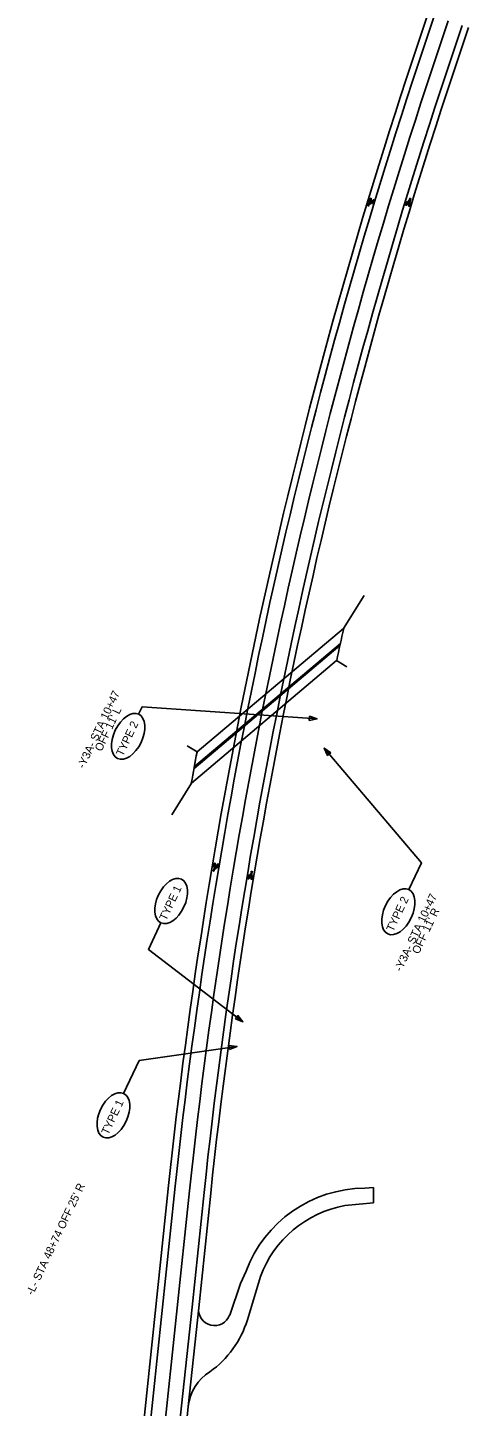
# Model space of a CAD drawing. Extents: x 553958 to 562499, y 493978 to 516388.
# Drawn here: x 561127 to 561457, y 496087 to 497120 of the extents above; entities that cross this region are included whole.
import ezdxf

# ---------------------------------------------------------------- set-up
doc = ezdxf.new("R2010")
doc.units = 0
for name, color, linetype in [('Default', 7, 'Continuous'), ('Prop DSN Text', 7, 'Continuous'), ('Prop EOT', 7, 'Continuous'), ('Prop Horizontal Alignment Tick Small', 7, 'Continuous'), ('Prop SS Fill Line', 7, 'Continuous'), ('Sheet Plan CELL', 7, 'Continuous'), ('Sheet Plot Border Inside CELL', 7, 'Continuous'), ('Sheet Plot Border Outside CELL', 7, 'Continuous')]:
    doc.layers.add(name, color=color, linetype=linetype)

msp = doc.modelspace()

# ---------------------------------------------------------------- linework, layer by layer
at = {"layer": 'Default'}
for p, q in [((561363.7, 496669.9), (561379.1, 496694.6)), ((561254, 496577.2), (561363.7, 496669.9)), ((561251.7, 496564.7), (561360.9, 496657)), ((561252, 496566.3), (561361.3, 496658.6)), ((561249.7, 496553.9), (561358.5, 496645.8)), ((561358.5, 496645.8), (561366.1, 496641.1)), ((561246.5, 496581.8), (561254, 496577.2)), ((561235, 496530.2), (561249.7, 496553.9))]:
    msp.add_line(p, q, dxfattribs=at)
for centre, radius, start, end in [((565242.2, 495812.8), 3972, 167.5396, 167.8948), ((565213, 495835.1), 4028, 169.3836, 169.72)]:
    msp.add_arc(centre, radius, start, end, dxfattribs=at)
at = {"layer": 'Prop DSN Text'}
for centre, major_axis, ratio in [((561202.4, 496588.9), (7.9, 16.6), 0.581481), ((561234.6, 496465.5), (7.7, 16.4), 0.582717), ((561404.7, 496457.4), (7.9, 16.6), 0.581481), ((561191.3, 496304.8), (7.7, 16.4), 0.582717)]:
    msp.add_ellipse(centre, major_axis=major_axis, ratio=ratio, dxfattribs=at)
at = {"layer": 'Prop EOT'}
for p, q in [((561250.2, 496160.9), (561242.4, 496087.1)), ((561247.4, 496086.6), (561255.2, 496160.4))]:
    msp.add_line(p, q, dxfattribs=at)
at = {"layer": 'Prop Horizontal Alignment Tick Small'}
for p, q in [((561383, 496991.4), (561383.2, 496991.2)), ((561383, 496991.4), (561383.2, 496991.2)), ((561383, 496989.3), (561384.6, 496990.7)), ((561384.8, 496990.5), (561383.3, 496989.2)), ((561383.9, 496990.8), (561384.1, 496990.7)), ((561383.9, 496990.8), (561384.1, 496990.7)), ((561384.6, 496990.7), (561384.8, 496990.5)), ((561413.3, 496990.9), (561412.1, 496990.1)), ((561412.1, 496990.1), (561412.2, 496990.4)), ((561412.2, 496990.4), (561413.3, 496991.2)), ((561413, 496991.9), (561413.2, 496991.9)), ((561413, 496991.9), (561413.2, 496991.9)), ((561413, 496989.8), (561413.3, 496990.9)), ((561413.3, 496991.2), (561413.7, 496991.2)), ((561413.7, 496991.2), (561413.3, 496989.5)), ((561413.9, 496991.6), (561414.1, 496991.6)), ((561413.9, 496991.6), (561414.1, 496991.6)), ((561381.9, 496987.4), (561381.8, 496987.5)), ((561381.9, 496987.4), (561381.8, 496987.5)), ((561382.3, 496987.8), (561383, 496989.3)), ((561382.6, 496987.7), (561382.3, 496987.8)), ((561383.9, 496988.2), (561382.6, 496987.7)), ((561382.8, 496986.9), (561382.6, 496987)), ((561382.8, 496986.9), (561382.6, 496987)), ((561383.2, 496989), (561382.7, 496988)), ((561382.7, 496988), (561384, 496988.4)), ((561384.2, 496988.9), (561383.2, 496989)), ((561383.3, 496989.2), (561384.1, 496989.1)), ((561384, 496988.4), (561383.9, 496988.2)), ((561384.1, 496989.1), (561384.3, 496989.7)), ((561384.5, 496989.7), (561384.2, 496988.9)), ((561384.3, 496989.7), (561384.5, 496989.7)), ((561385.1, 496990.2), (561385.3, 496990)), ((561385.1, 496990.2), (561385.3, 496990)), ((561386, 496989.6), (561386.2, 496989.5)), ((561386, 496989.6), (561386.2, 496989.5)), ((561410.5, 496988.5), (561410.3, 496988.6)), ((561410.5, 496988.5), (561410.3, 496988.6)), ((561411.5, 496988.2), (561411.3, 496988.3)), ((561411.5, 496988.2), (561411.3, 496988.3)), ((561411.8, 496988), (561413, 496989.6)), ((561412, 496987.8), (561411.8, 496987.9)), ((561412, 496989.7), (561413, 496989.8)), ((561412, 496988.9), (561412, 496989.7)), ((561413.3, 496989.5), (561412, 496987.8)), ((561412.2, 496988.8), (561412, 496988.9)), ((561413, 496989.6), (561412.2, 496989.5)), ((561412.2, 496989.5), (561412.2, 496988.8)), ((561412.8, 496987.8), (561412.6, 496987.9)), ((561412.8, 496987.8), (561412.6, 496987.9)), ((561413.8, 496987.5), (561413.6, 496987.6)), ((561413.8, 496987.5), (561413.6, 496987.6)), ((561266.1, 496488.6), (561266, 496488.7)), ((561266.1, 496488.6), (561266, 496488.7)), ((561266.2, 496492.7), (561266.5, 496492.7)), ((561266.2, 496492.7), (561266.5, 496492.7)), ((561266.4, 496489.1), (561266.8, 496490.7)), ((561266.7, 496489.1), (561266.4, 496489.1)), ((561267.9, 496489.8), (561266.7, 496489.1)), ((561266.8, 496490.7), (561268, 496492.4)), ((561267, 496490.5), (561266.8, 496489.4)), ((561266.8, 496489.4), (561268, 496490.1)), ((561267, 496488.4), (561266.9, 496488.4)), ((561267, 496488.4), (561266.9, 496488.4)), ((561268.2, 496492.3), (561267, 496490.7)), ((561267, 496490.7), (561267.8, 496490.8)), ((561268, 496490.6), (561267, 496490.5)), ((561267.2, 496492.4), (561267.5, 496492.3)), ((561267.2, 496492.4), (561267.5, 496492.3)), ((561267.8, 496490.8), (561267.9, 496491.4)), ((561267.9, 496491.4), (561268.1, 496491.4)), ((561268, 496490.1), (561267.9, 496489.8)), ((561268, 496492.4), (561268.2, 496492.3)), ((561268.1, 496491.4), (561268, 496490.6)), ((561268.6, 496492), (561268.8, 496491.9)), ((561268.6, 496492), (561268.8, 496491.9)), ((561269.6, 496491.7), (561269.8, 496491.6)), ((561269.6, 496491.7), (561269.8, 496491.6)), ((561293.6, 496484.9), (561294.6, 496485.1)), ((561293.6, 496483.2), (561294.6, 496484.9)), ((561293.6, 496484.1), (561293.6, 496484.9)), ((561293.9, 496484.1), (561293.6, 496484.1)), ((561293.7, 496485.7), (561294.8, 496486.5)), ((561294.8, 496486.2), (561293.7, 496485.4)), ((561293.7, 496485.4), (561293.7, 496485.7)), ((561294.9, 496484.9), (561293.8, 496483)), ((561294.6, 496484.9), (561293.9, 496484.7)), ((561293.9, 496484.7), (561293.9, 496484.1)), ((561294.4, 496487.2), (561294.5, 496487.2)), ((561294.4, 496487.2), (561294.5, 496487.2)), ((561294.6, 496485.1), (561294.8, 496486.2)), ((561294.8, 496486.5), (561295.1, 496486.5)), ((561295.1, 496486.5), (561294.9, 496484.9)), ((561295.3, 496487), (561295.5, 496487)), ((561295.3, 496487), (561295.5, 496487)), ((561292.2, 496483.6), (561292, 496483.6)), ((561292.2, 496483.6), (561292, 496483.6)), ((561293.2, 496483.4), (561293, 496483.4)), ((561293.2, 496483.4), (561293, 496483.4)), ((561293.8, 496483), (561293.6, 496483.1)), ((561294.6, 496483.1), (561294.4, 496483.2)), ((561294.6, 496483.1), (561294.4, 496483.2)), ((561295.6, 496482.9), (561295.4, 496483)), ((561295.6, 496482.9), (561295.4, 496483))]:
    msp.add_line(p, q, dxfattribs=at)
for centre, radius, start, end in [((561413.5, 496991.7), 0.563, 343.4971, 163.4971), ((561413.5, 496991.7), 0.563, 343.4971, 163.4971), ((561413.5, 496991.7), 0.41, 163.4971, 343.4971), ((561382.3, 496987.2), 0.563, 150.099, 330.099), ((561382.3, 496987.2), 0.563, 150.099, 330.099), ((561382.3, 496987.2), 0.41, 330.099, 150.099), ((561266.5, 496488.5), 0.563, 163.2488, 343.2488), ((561266.5, 496488.5), 0.563, 163.2488, 343.2488), ((561266.5, 496488.5), 0.41, 343.2488, 163.2488), ((561294.9, 496487.1), 0.563, 349.0068, 169.0068), ((561294.9, 496487.1), 0.563, 349.0068, 169.0068), ((561294.9, 496487.1), 0.41, 169.0068, 349.0068)]:
    msp.add_arc(centre, radius, start, end, dxfattribs=at)
for centre, major_axis, ratio, start_param, end_param in [((561383.5, 496991), (0.75, 1.3), 0.435841, 1.570796, 4.712389), ((561383.5, 496991), (0.62, 1.08), 0.325967, 1.570796, 4.712389), ((561383.5, 496991), (0.75, 1.3), 0.435841, 4.712389, 7.853982), ((561383.5, 496991), (0.62, 1.08), 0.325967, 4.712389, 7.853982), ((561385.6, 496989.8), (0.75, 1.3), 0.435841, 4.712389, 7.853982), ((561385.6, 496989.8), (0.62, 1.08), 0.325967, 4.712389, 7.853982), ((561385.6, 496989.8), (0.75, 1.3), 0.435841, 1.570796, 4.712389), ((561385.6, 496989.8), (0.62, 1.08), 0.325967, 1.570796, 4.712389), ((561410.9, 496988.4), (-0.42, -1.43), 0.435841, 4.712389, 7.853982), ((561410.9, 496988.4), (-0.42, -1.43), 0.435841, 1.570796, 4.712389), ((561410.9, 496988.4), (-0.36, -1.2), 0.325967, 4.712389, 7.853982), ((561410.9, 496988.4), (-0.36, -1.2), 0.325967, 1.570796, 4.712389), ((561413.2, 496987.7), (-0.42, -1.43), 0.435841, 4.712389, 7.853982), ((561413.2, 496987.7), (-0.42, -1.43), 0.435841, 1.570796, 4.712389), ((561413.2, 496987.7), (-0.36, -1.2), 0.325967, 4.712389, 7.853982), ((561413.2, 496987.7), (-0.36, -1.2), 0.325967, 1.570796, 4.712389), ((561266.9, 496492.5), (0.43, 1.43), 0.435841, 1.570796, 4.712389), ((561266.9, 496492.5), (0.43, 1.43), 0.435841, 4.712389, 7.853982), ((561266.9, 496492.5), (0.36, 1.2), 0.325967, 1.570796, 4.712389), ((561266.9, 496492.5), (0.36, 1.2), 0.325967, 4.712389, 7.853982), ((561269.2, 496491.8), (0.43, 1.43), 0.435841, 1.570796, 4.712389), ((561269.2, 496491.8), (0.43, 1.43), 0.435841, 4.712389, 7.853982), ((561269.2, 496491.8), (0.36, 1.2), 0.325967, 1.570796, 4.712389), ((561269.2, 496491.8), (0.36, 1.2), 0.325967, 4.712389, 7.853982), ((561292.6, 496483.5), (-0.29, -1.47), 0.435841, 1.570796, 4.712389), ((561292.6, 496483.5), (-0.24, -1.23), 0.325967, 1.570796, 4.712389), ((561295, 496483.1), (-0.29, -1.47), 0.435841, 1.570796, 4.712389), ((561295, 496483.1), (-0.24, -1.23), 0.325967, 1.570796, 4.712389), ((561292.6, 496483.5), (-0.29, -1.47), 0.435841, 4.712389, 7.853982), ((561292.6, 496483.5), (-0.24, -1.23), 0.325967, 4.712389, 7.853982), ((561295, 496483.1), (-0.29, -1.47), 0.435841, 4.712389, 7.853982), ((561295, 496483.1), (-0.24, -1.23), 0.325967, 4.712389, 7.853982)]:
    msp.add_ellipse(centre, major_axis=major_axis, ratio=ratio, start_param=start_param, end_param=end_param, dxfattribs=at)
at = {"layer": 'Prop SS Fill Line'}
for p, q in [((561414.8, 497094.4), (561426.8, 497130.4)), ((561445.2, 497084.3), (561457.2, 497120.3)), ((561190.5, 495851.5), (561232.4, 496249.8)), ((561255.2, 496160.4), (561264.2, 496246.5)), ((561386.1, 496250.6), (561379.6, 496250.2)), ((561386.2, 496239.3), (561386.1, 496250.6)), ((561364.7, 496237.2), (561386.2, 496239.3)), ((561286.5, 496178.8), (561290.7, 496187.9)), ((561278.4, 496154.9), (561286.5, 496178.8)), ((561291.7, 496151.5), (561301.4, 496183.9)), ((561222.3, 495848.1), (561247.4, 496086.6))]:
    msp.add_line(p, q, dxfattribs=at)
for centre, radius, start, end in [((565226.3, 495829.2), 4016, 161.6362, 173.9875), ((565226.3, 495829.2), 3984, 161.6362, 173.9875), ((561380.3, 496154.5), 95.7, 90.4491, 159.5498), ((561380.3, 496154.5), 84.2, 100.7272, 159.5498), ((561267.1, 496159.1), 12, 173.9875, 339.5498), ((561220.3, 496173.3), 74.6, 305.4505, 342.9447), ((561282.2, 496082.9), 35, 122.0555, 173.9875)]:
    msp.add_arc(centre, radius, start, end, dxfattribs=at)
at = {"layer": 'Sheet Plan CELL'}
for points in [[(561210.2, 496605.5), (561212.8, 496611), (561343.9, 496602)], [(561412.6, 496474), (561422, 496494), (561349.2, 496580.1)], [(561226.9, 496449.1), (561217.5, 496429.2), (561288.3, 496374.9)], [(561199, 496321.2), (561210.7, 496345.9), (561283.8, 496356.5)]]:
    msp.add_lwpolyline(points, dxfattribs=at)
for points in [[(561338, 496600.9), (561343.9, 496602), (561338.2, 496604)], [(561354.1, 496576.6), (561349.2, 496580.1), (561351.7, 496574.6)], [(561282.7, 496377.2), (561288.3, 496374.9), (561284.6, 496379.6)], [(561278.3, 496354.1), (561283.8, 496356.5), (561277.8, 496357.2)]]:
    msp.add_lwpolyline(points, close=True, dxfattribs=at)
at = {"layer": 'Sheet Plot Border Inside CELL'}
for p, q in [((561414.8, 497094.4), (561426.8, 497130.4)), ((561419.6, 497092.9), (561431.5, 497128.8)), ((561440.5, 497085.9), (561452.4, 497121.9)), ((561445.2, 497084.3), (561457.2, 497120.3)), ((561190.5, 495851.5), (561232.4, 496249.8)), ((561195.4, 495851), (561237.4, 496249.3)), ((561250.2, 496160.9), (561259.3, 496247)), ((561255.2, 496160.4), (561264.2, 496246.5)), ((561386.1, 496250.6), (561379.6, 496250.2)), ((561364.7, 496237.2), (561386.2, 496239.3)), ((561286.5, 496178.8), (561290.7, 496187.9)), ((561278.4, 496154.9), (561286.5, 496178.8)), ((561291.7, 496151.5), (561301.4, 496183.9)), ((561217.3, 495848.7), (561242.4, 496087.1)), ((561222.3, 495848.1), (561247.4, 496086.6))]:
    msp.add_line(p, q, dxfattribs=at)
for centre, radius, start, end in [((565226.3, 495829.2), 4016, 161.6362, 173.9875), ((565226.3, 495829.2), 4011, 161.6362, 173.9875), ((565226.3, 495829.2), 3989, 161.6362, 173.9875), ((565226.3, 495829.2), 3984, 161.6362, 173.9875), ((561380.3, 496154.5), 95.7, 90.4491, 159.5498), ((561380.3, 496154.5), 84.2, 100.7272, 159.5498), ((561267.1, 496159.1), 12, 173.9875, 339.5498), ((561220.3, 496173.3), 74.6, 305.4505, 342.9447), ((561282.2, 496082.9), 35, 122.0555, 173.9875)]:
    msp.add_arc(centre, radius, start, end, dxfattribs=at)
at = {"layer": 'Sheet Plot Border Outside CELL'}
for p, q in [((561430, 497089.4), (561442, 497125.4)), ((561206.4, 495849.8), (561248.3, 496248.2))]:
    msp.add_line(p, q, dxfattribs=at)
msp.add_arc((565226.3, 495829.2), 4000, 161.6362, 173.9875, dxfattribs=at)

# ---------------------------------------------------------------- texts
at = {"layer": 'Prop EOT'}
for s, p in [('-Y3A- STA 10+47', (561169.4, 496564.3)), ("OFF 11' L", (561182.4, 496577.1)), ('TYPE 2', (561198.4, 496573.5)), ('TYPE 1', (561230.8, 496450.3)), ('TYPE 2', (561400.8, 496442)), ('-Y3A- STA 10+47', (561406.9, 496412.1)), ("OFF 11' R", (561420, 496425.2)), ('TYPE 1', (561187.4, 496289.7)), ("-L- STA 48+74 OFF 25' R", (561131.1, 496169.5))]:
    msp.add_text(s, height=6, rotation=64.7021, dxfattribs=at).set_placement(p)

doc.saveas('drawing.dxf')
